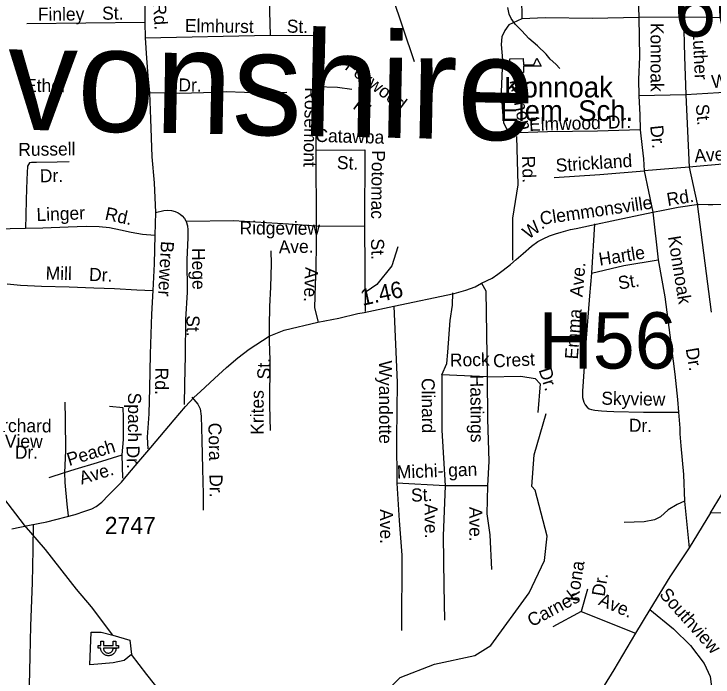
# Model space of a CAD drawing. Extents: x 1553981 to 1780076, y 812965 to 996873.
# Drawn here: x 1632965 to 1633602, y 845527 to 846130 of the extents above; entities that cross this region are included whole.
import ezdxf

# ---------------------------------------------------------------- set-up
doc = ezdxf.new("R2010")
doc.units = 0
for name, color, linetype in [('Exist Aviation Coast Guard Station CELL', 7, 'Continuous'), ('Exist Cultural Educational Facility High Label', 7, 'Continuous'), ('Exist Cultural Historical Site CELL', 7, 'Continuous'), ('Exist Hydrographic Creek Single Shore', 7, 'Continuous'), ('Exist Hydrographic Misc Water Feature', 7, 'Continuous'), ('Exist Road Non-System Type 51 Label', 7, 'Continuous'), ('Exist Road Primary US Structure Non-Sys NCDOT Number Label', 7, 'Continuous'), ('Exist Road Secondary Mileage Hundredths English Label', 7, 'Continuous'), ('Exist Road Secondary Structure Standard Bridge Number Label', 7, 'Continuous'), ('Exist Road Secondary Type 51 Attributed', 7, 'Continuous'), ('Exist Road Secondary Type 51 Number Label', 7, 'Continuous'), ('Exist Utilities Electrical Transmission Line', 7, 'Continuous'), ('Map Preparation Border Antique Large Shape', 7, 'Continuous'), ('Map Preparation Border County Name Lower Right Label', 7, 'Continuous')]:
    doc.layers.add(name, color=color, linetype=linetype)

msp = doc.modelspace()

# ---------------------------------------------------------------- linework, layer by layer
at = {"layer": 'Exist Aviation Coast Guard Station CELL'}
msp.add_lwpolyline([(1633416.81, 846089.49), (1633429.05, 846089.67), (1633429.14, 846083.92), (1633438.52, 846084.06), (1633441.46, 846089.99), (1633445.22, 846082.97), (1633429.15, 846082.72), (1633429.24, 846076.97), (1633417, 846076.78)], close=True, dxfattribs=at)
at = {"layer": 'Exist Cultural Historical Site CELL'}
msp.add_lwpolyline([(1633041.73, 845555.6), (1633044.17, 845555.6), (1633044.17, 845559.63), (1633046.65, 845559.63), (1633046.65, 845555.6), (1633055.5, 845555.6), (1633055.5, 845559.63), (1633057.98, 845559.63), (1633057.98, 845555.6), (1633060.42, 845555.6), (1633060.42, 845553.17), (1633057.98, 845553.17), (1633055.5, 845553.17), (1633046.65, 845553.17), (1633046.73, 845552.4), (1633046.88, 845551.73), (1633047.18, 845551.03), (1633047.65, 845550.36), (1633048.23, 845549.75), (1633048.56, 845549.51), (1633048.94, 845549.3), (1633049.41, 845549.04), (1633049.93, 845548.87), (1633050.53, 845548.75), (1633050.99, 845548.72), (1633051.51, 845548.74), (1633052.1, 845548.83), (1633052.63, 845548.98), (1633053.01, 845549.13), (1633053.42, 845549.35), (1633053.84, 845549.65), (1633054.24, 845550), (1633054.57, 845550.37), (1633054.84, 845550.74), (1633055, 845551.03), (1633055.18, 845551.38), (1633055.35, 845551.82), (1633055.41, 845552.1), (1633055.51, 845552.56), (1633055.54, 845552.92), (1633055.56, 845553.17), (1633058.26, 845553.17), (1633058.22, 845552.74), (1633058.18, 845552.41), (1633058.11, 845552), (1633058.01, 845551.58), (1633057.88, 845551.11), (1633057.75, 845550.72), (1633057.59, 845550.32), (1633057.36, 845549.88), (1633057.07, 845549.43), (1633056.76, 845548.98), (1633056.43, 845548.6), (1633056.1, 845548.26), (1633055.65, 845547.86), (1633055.18, 845547.49), (1633054.65, 845547.18), (1633054.1, 845546.9), (1633053.68, 845546.72), (1633053.29, 845546.59), (1633052.9, 845546.49), (1633052.42, 845546.38), (1633051.96, 845546.33), (1633051.53, 845546.28), (1633050.98, 845546.28), (1633050.6, 845546.3), (1633050.17, 845546.35), (1633049.72, 845546.44), (1633049.12, 845546.58), (1633048.49, 845546.82), (1633047.94, 845547.07), (1633047.49, 845547.33), (1633046.97, 845547.67), (1633046.58, 845548), (1633046.34, 845548.2), (1633046.03, 845548.51), (1633045.79, 845548.79), (1633045.45, 845549.2), (1633045.11, 845549.74), (1633044.87, 845550.2), (1633044.67, 845550.62), (1633044.53, 845551.01), (1633044.33, 845551.66), (1633044.23, 845552.21), (1633044.17, 845552.68), (1633044.13, 845553.17), (1633041.73, 845553.17)], close=True, dxfattribs=at)
at = {"layer": 'Exist Hydrographic Creek Single Shore'}
for points in [[(1633329.83, 846086.82), (1633309.7, 846147.54), (1633282.73, 846197.75)], [(1633273.69, 845479.99), (1633291.58, 845501.65), (1633316.82, 845526.57), (1633348.33, 845538.66), (1633384.82, 845546.53), (1633399.58, 845555.67), (1633434.46, 845603.38), (1633448.33, 845633.05), (1633450.71, 845655.16), (1633439.83, 845696.82), (1633436.7, 845700.17), (1633439.07, 845729.25), (1633449.95, 845766.78)]]:
    msp.add_lwpolyline(points, dxfattribs=at)
at = {"layer": 'Exist Hydrographic Misc Water Feature'}
msp.add_lwpolyline([(1633462.42, 846080.77), (1633458.71, 846084.8), (1633453.49, 846089.33), (1633449.79, 846093.61), (1633441.84, 846101.42), (1633434.15, 846107.97), (1633427.71, 846115.02), (1633421.5, 846121.06), (1633418.04, 846126.09), (1633416.07, 846130.11), (1633414.86, 846136.11)], dxfattribs=at)
at = {"layer": 'Exist Road Secondary Type 51 Attributed'}
msp.add_lwpolyline([(1632963.12, 845661.71), (1632979.22, 845665.01), (1632995.26, 845668.13), (1633020.94, 845674.7), (1633029.82, 845677.7), (1633036.23, 845679.82), (1633040.09, 845682.04), (1633045.1, 845686.14), (1633051.43, 845692.47), (1633063.1, 845704.31), (1633068.81, 845711.18), (1633078.76, 845722.98), (1633089.74, 845735.85), (1633110.97, 845760.98), (1633121.51, 845773.19), (1633129.01, 845781.21), (1633134.94, 845786.77), (1633147.71, 845798.61), (1633158.84, 845808.56), (1633169.01, 845817.31), (1633179.25, 845825.18), (1633197.47, 845836.99), (1633211.17, 845842.53), (1633242, 845849.91), (1633260.97, 845853.6), (1633278.5, 845857.64), (1633284.06, 845858.55), (1633311.25, 845864.47), (1633366.07, 845876.06), (1633376.69, 845879.1), (1633385.3, 845882.07), (1633391.09, 845885.27), (1633400.59, 845890.02), (1633405.86, 845893.5), (1633410.76, 845897.29), (1633417.44, 845902.26), (1633422.56, 845906.79), (1633428.87, 845912.28), (1633436.51, 845918.96), (1633442.37, 845923.27), (1633447.05, 845925.72), (1633452.84, 845928.31), (1633458.41, 845930.24), (1633463.53, 845931.88), (1633472.08, 845934.09), (1633477.18, 845935.14), (1633491.21, 845938.19), (1633513.92, 845942.86), (1633547.03, 845949.91), (1633556.38, 845951.84), (1633570.19, 845954.44), (1633588.84, 845957.1), (1633597.32, 845957.09), (1633601.71, 845957.09), (1633609.34, 845957.39)], dxfattribs=at)
at = {"layer": 'Exist Utilities Electrical Transmission Line'}
for points in [[(1633055.15, 845565.05), (1633035.83, 845590.83), (1633022.08, 845606.79), (1632993.94, 845642.95), (1632974.81, 845665.23), (1632955.95, 845689.75)], [(1633072.35, 845547.29), (1633065.53, 845541.9), (1633055.51, 845539.8), (1633045.24, 845538.96), (1633034.24, 845538.13), (1633035.47, 845567.85), (1633044.7, 845567.71), (1633055.15, 845565.05)], [(1633055.15, 845565.05), (1633070.81, 845560.3), (1633072.35, 845547.29)], [(1633102.52, 845052.3), (1633102.88, 845058.57), (1633107.42, 845124.47), (1633110.13, 845170.89), (1633112.76, 845195.6), (1633114.2, 845223.31), (1633115.03, 845243.53), (1633118.05, 845277.46), (1633121.98, 845335.64), (1633126.04, 845403.79), (1633129.56, 845452.95), (1633129.62, 845473.18), (1633115.46, 845492.41), (1633086.06, 845529.07), (1633072.35, 845547.29)]]:
    msp.add_lwpolyline(points, dxfattribs=at)
at = {"layer": 'Map Preparation Border County Name Lower Right Label'}
for p, q in [((1633426.71, 846173.05), (1633427.7, 846126.04)), ((1633575.03, 846127.38), (1633534.21, 846127.07)), ((1633619.65, 846126.83), (1633575.03, 846127.38)), ((1633622.48, 846059.42), (1633577.09, 846056.8)), ((1633577.09, 846056.8), (1633534.14, 846055.83)), ((1633577.09, 846056.8), (1633580.15, 845991.06)), ((1633284.68, 846006.55), (1633284.33, 845937.57)), ((1633619.6, 845994.64), (1633580.15, 845991.06)), ((1633580.15, 845991.06), (1633539.02, 845987.66)), ((1633580.15, 845991.06), (1633587.34, 845957.42)), ((1633539.02, 845987.66), (1633547.03, 845949.91)), ((1633587.34, 845957.42), (1633600.22, 845859.06)), ((1633547.03, 845949.91), (1633551.98, 845906.73)), ((1633094.19, 845949.77), (1633093.62, 845929.04)), ((1633284.33, 845937.57), (1633284.97, 845859.44)), ((1633494, 845939.29), (1633491.12, 845894.57)), ((1633314.86, 845918.27), (1633309.45, 845901.26)), ((1633309.45, 845901.26), (1633295.54, 845884.24)), ((1633295.54, 845884.24), (1633286.1, 845877.5)), ((1633064.45, 845707.85), (1633063.85, 845729.13)), ((1632997.35, 845708.4), (1633011.17, 845712.92)), ((1633357.88, 845700.95), (1633313.89, 845703.3)), ((1633575.85, 845686.94), (1633580.17, 845644.56)), ((1633599.64, 845676.37), (1633580.17, 845644.56))]:
    msp.add_line(p, q, dxfattribs=at)
for points in [[(1633570.16, 846236.74), (1633573.04, 846170.24), (1633575.03, 846127.38)], [(1633534.1, 846168.98), (1633533.6, 846146), (1633534.21, 846127.07)], [(1633197.29, 846154.82), (1633198.38, 846111.08)], [(1633084.52, 846152.04), (1633084.52, 846122.53)], [(1633084.52, 846122.53), (1632977.01, 846121.49)], [(1633084.52, 846122.53), (1633084.58, 846108.65)], [(1633427.7, 846126.04), (1633415.78, 846120.36), (1633412.28, 846115.42), (1633409.61, 846109.45), (1633408.99, 846102.46), (1633410.23, 846088.47), (1633408.99, 846059.25), (1633410.23, 846041.23), (1633411.06, 846031.56), (1633413.73, 846025.8), (1633416.2, 846021.89)], [(1633534.21, 846127.07), (1633492.15, 846126.25), (1633449.16, 846126.87), (1633427.7, 846126.04)], [(1633534.21, 846127.07), (1633534.96, 846091.22), (1633533.93, 846070.85), (1633534.14, 846055.83)], [(1633575.03, 846127.38), (1633575.85, 846091.58), (1633577.09, 846056.8)], [(1633084.58, 846108.65), (1633198.38, 846111.08)], [(1633198.38, 846111.08), (1633240.54, 846110.8)], [(1633240.54, 846110.8), (1633240.2, 846064.27)], [(1633084.58, 846108.65), (1633085.96, 846090.24), (1633087.01, 846073.92), (1633088.51, 846058.43)], [(1633213.7, 846058.99), (1633196.93, 846058.43), (1633175.14, 846058.99), (1633158.37, 846059.55), (1633137.69, 846058.43), (1633115.9, 846057.87), (1633088.51, 846058.43)], [(1633088.51, 846058.43), (1633089.63, 846034.95), (1633090.19, 846017.61), (1633090.75, 846000.28), (1633092.99, 845976.79), (1633094.19, 845949.77)], [(1633240.2, 846064.27), (1633259.98, 846063.58), (1633272.81, 846061.84)], [(1633240.2, 846064.27), (1633240.21, 846006.42)], [(1633534.14, 846055.83), (1633535.25, 846038.56), (1633535.58, 846024.96)], [(1633535.58, 846024.96), (1633496.59, 846023.54), (1633451.15, 846023.13), (1633416.2, 846021.89)], [(1633535.58, 846024.96), (1633537.17, 846008.86), (1633538.61, 845998.57), (1633539.02, 845987.66)], [(1633422.73, 846018.88), (1633424.09, 845974.88), (1633419.28, 845944.36), (1633419.08, 845906.13)], [(1633240.21, 846006.42), (1633284.68, 846006.55)], [(1633240.21, 846006.42), (1633240.55, 845937.32)], [(1633015.46, 845995.66), (1633004.47, 845995.34), (1632985.73, 845995.12), (1632981.23, 845995.18), (1632979.22, 845994.97), (1632977.43, 845991.73), (1632977.01, 845979.76), (1632976.22, 845961.54), (1632976, 845946.79), (1632975.59, 845935.31)], [(1633457.14, 845981.58), (1633498.64, 845984.24), (1633539.02, 845987.66)], [(1633094.19, 845949.77), (1633101.71, 845951.42), (1633105.31, 845951.69), (1633108.61, 845951.45), (1633111.97, 845950.61), (1633114.65, 845949.45), (1633116.7, 845948.16), (1633118.37, 845946.65), (1633120.35, 845944.26), (1633121.58, 845942.15)], [(1633599.64, 845676.37), (1633646.27, 845752.81), (1633660.34, 845775.98), (1633666.77, 845790.5), (1633670.58, 845802.82), (1633672.92, 845814.84), (1633673.51, 845827.75), (1633673.51, 845865.59), (1633668.81, 845911.16), (1633666.76, 845955.46)], [(1632975.59, 845935.31), (1632991.33, 845935.82), (1633014.56, 845936.72), (1633030.81, 845937.22), (1633042.78, 845936.8), (1633052.27, 845935.91), (1633062.23, 845933.76), (1633071.94, 845931.61), (1633082.14, 845929.98), (1633093.62, 845929.04)], [(1633121.58, 845942.15), (1633122.04, 845941.35), (1633123.16, 845937.52), (1633123.41, 845933.84), (1633123.55, 845926.83), (1633123.2, 845919.86), (1633122.76, 845906.86), (1633123.06, 845877.14), (1633121.34, 845852.29), (1633121.09, 845819.46), (1633120.44, 845793.49), (1633120.3, 845774.85)], [(1633240.55, 845937.32), (1633215.23, 845939.18), (1633165.27, 845941.95), (1633122.24, 845941.61)], [(1633240.55, 845937.32), (1633240.32, 845921.31), (1633239.98, 845898.33), (1633239.39, 845884.18), (1633238.81, 845862.96), (1633242.15, 845849.94)], [(1633240.55, 845937.32), (1633284.33, 845937.57)], [(1632943.6, 845934.29), (1632961.85, 845935.02), (1632975.59, 845935.31)], [(1633093.62, 845929.04), (1633092.97, 845902.82), (1633091.6, 845878.61)], [(1633199.04, 845914.72), (1633199.38, 845902.98), (1633198.8, 845881.73), (1633197.79, 845864.02), (1633197.75, 845846.29), (1633197.54, 845832.31)], [(1633491.12, 845894.57), (1633520.52, 845901.38), (1633551.98, 845906.73)], [(1633551.98, 845906.73), (1633557.94, 845872.98), (1633562.47, 845838.11), (1633567, 845802.51), (1633569.47, 845779.43), (1633570.5, 845767.9)], [(1633491.12, 845894.57), (1633489.42, 845873.84), (1633486.06, 845831.37), (1633482.93, 845787.16), (1633483.11, 845781.15), (1633484.08, 845777.15), (1633485.55, 845774.64), (1633487.28, 845772.38), (1633489.03, 845771.1), (1633491.27, 845770.35), (1633494.11, 845769.62), (1633500.25, 845769.02), (1633504.99, 845768.72), (1633511.49, 845768.41), (1633538.47, 845767.94), (1633570.5, 845767.9)], [(1632959.08, 845884.6), (1632971.06, 845883.4), (1632990.28, 845882.64), (1633015.48, 845882), (1633037.95, 845881.17), (1633056.67, 845880.39), (1633077.13, 845879.32), (1633091.6, 845878.61)], [(1633391.09, 845885.27), (1633394.79, 845878.31), (1633396.25, 845800.25)], [(1633091.6, 845878.61), (1633090.54, 845857.14), (1633089.22, 845820.67), (1633088.5, 845789.72), (1633087.9, 845766.49), (1633086.59, 845745.28), (1633087.09, 845734.67)], [(1633354.94, 845802.04), (1633359.34, 845812.32), (1633360.21, 845822.59), (1633362.56, 845851.35), (1633364.61, 845865.43), (1633364.78, 845876.55)], [(1633311.25, 845864.47), (1633314.18, 845794.91), (1633313.59, 845744.09), (1633313.89, 845703.3)], [(1633197.54, 845832.31), (1633198.16, 845815.63), (1633198.01, 845773.91), (1633198.42, 845751.17)], [(1633354.94, 845802.04), (1633354.94, 845751.43), (1633357.88, 845700.95)], [(1633396.25, 845800.25), (1633354.94, 845802.04)], [(1633396.25, 845800.25), (1633426.75, 845800.83), (1633439.95, 845798.48), (1633444.35, 845793.79), (1633442.29, 845767.67)], [(1633396.25, 845800.25), (1633396.55, 845761.65), (1633397.73, 845723.2), (1633396.55, 845700.9)], [(1633127.1, 845781.56), (1633132.6, 845775.14), (1633134.79, 845770.87), (1633135.68, 845764.35), (1633136.37, 845742.6), (1633136.96, 845716.37), (1633137.37, 845693.37), (1633137.62, 845678.89)], [(1633011.4, 845777.13), (1633011.91, 845761.63), (1633011.98, 845732.89), (1633011.17, 845712.92)], [(1633063.85, 845729.13), (1633064.81, 845743.1), (1633064.87, 845763.33), (1633064.5, 845771.85), (1633052.29, 845773.02)], [(1633570.5, 845767.9), (1633571.75, 845753.3), (1633571.7, 845748.3), (1633572.55, 845737.24), (1633574.81, 845711.11), (1633575.85, 845686.94)], [(1633011.17, 845712.92), (1633020.94, 845716.02), (1633041.28, 845722.21), (1633063.85, 845729.13)], [(1633011.17, 845712.92), (1633011.52, 845703.93), (1633013.47, 845684.16), (1633014.47, 845673.68)], [(1633313.89, 845703.3), (1633316.03, 845669.45), (1633318.31, 845637.71), (1633318.09, 845569.11)], [(1633357.88, 845700.95), (1633356.11, 845655.33), (1633356.7, 845609.84), (1633357.28, 845578.73)], [(1633396.55, 845700.9), (1633357.88, 845700.95)], [(1633396.55, 845700.9), (1633395.96, 845675.48), (1633398.6, 845656.21), (1633400.07, 845624.81)], [(1633575.85, 845686.94), (1633569.06, 845684.06), (1633561.04, 845678.92), (1633554.05, 845672.54), (1633548.5, 845669.86), (1633539.04, 845668.01), (1633520.95, 845667.4)], [(1633687.83, 845675.15), (1633599.64, 845676.37)], [(1632982.66, 845666.1), (1632982.31, 845642.82), (1632981.83, 845612.47), (1632980.14, 845573.5), (1632979.66, 845545.56), (1632978.94, 845519.42), (1632978.22, 845501.12)], [(1633580.17, 845644.56), (1633562.64, 845618.21), (1633544.45, 845588.45)], [(1633487.57, 845606.94), (1633481.8, 845586.43)], [(1633544.45, 845588.45), (1633531.17, 845566.78)], [(1633544.45, 845588.45), (1633565.76, 845570.67), (1633581.35, 845555.65), (1633593.76, 845539.18), (1633599.25, 845527.34), (1633600.98, 845513.47), (1633600.69, 845486.89), (1633600.98, 845449.04)], [(1633481.8, 845586.43), (1633456.1, 845572.56)], [(1633481.8, 845586.43), (1633531.17, 845566.78)], [(1633531.17, 845566.78), (1633511.61, 845533.41), (1633491.4, 845501.05)]]:
    msp.add_lwpolyline(points, dxfattribs=at)

# ---------------------------------------------------------------- texts
at = {"layer": 'Exist Cultural Educational Facility High Label'}
for s, p in [('Konnoak', (1633411.68, 846054.36)), ('Elem. Sch.', (1633407.97, 846033))]:
    msp.add_text(s, height=18.75, dxfattribs=at).set_placement(p)
at = {"layer": 'Exist Road Non-System Type 51 Label'}
for s, height, rotation, p in [('Finley', 11.875, 0.37648, (1632986.94, 846124.14)), ('St.', 11.875, 0.56022, (1633045.52, 846125.06)), ('Rd.', 11.875, 273.85034, (1633091.68, 846140.18)), ('Devonshire', 95, 358.76379, (1632796.19, 846028.75)), ('Elmhurst', 11.875, 359.14646, (1633120.8, 846113.91)), ('St.', 11.875, 358.46822, (1633213.5, 846113.42)), ('Konnoak', 11.875, 270.01923, (1633544.94, 846122.29)), ('Luther', 11.875, 272.64198, (1633583.26, 846115.14)), ('Foxwood', 11.875, 323.10933, (1633265.71, 846080.56)), ('Ethel', 11.875, 359.64336, (1632975.26, 846059.39)), ('Dr.', 11.875, 359.74991, (1633114.94, 846059.82)), ('W.', 11.875, 5.0355, (1633600.92, 846062.78)), ('Renon', 11.875, 281.56932, (1633416.4, 846069.7)), ('Rosemont', 11.875, 268.79123, (1633230.31, 846063.63)), ('Pl.', 11.875, 323.10933, (1633273.03, 846044.84)), ('St.', 11.875, 274.83509, (1633586.13, 846047.88)), ('Elmwood', 11.875, 1.52977, (1633434.44, 846023.89)), ('Dr.', 11.875, 1.45903, (1633506.18, 846025.98)), ('Dr.', 11.875, 275.69149, (1633544.57, 846028.52)), ('Catawba', 11.875, 358.37073, (1633239.62, 846013.98)), ('Russell', 11.875, 0.67331, (1632969.19, 846001.07)), ('Ave.', 11.875, 4.03992, (1633585.23, 845995.31)), ('St.', 11.875, 358.37073, (1633259.17, 845989.24)), ('Potomac', 11.875, 269.26962, (1633291.23, 846006.44)), ('Strickland', 11.875, 3.87231, (1633458.98, 845986.59)), ('Rd.', 11.875, 271.7665, (1633427.77, 846001.09)), ('Dr.', 11.875, 0.67331, (1632988.78, 845977.12)), ('Linger', 11.875, 2.23018, (1632985.94, 845941.77)), ('Rd.', 11.875, 347.80379, (1633047.34, 845943.27)), ('Ridgeview', 11.875, 359.67818, (1633170.62, 845929.76)), ('St.', 11.875, 271.69191, (1633290.25, 845925.83)), ('Konnoak', 11.875, 279.13176, (1633560.68, 845927.52)), ('Brewer', 11.875, 266.90832, (1633099.15, 845923.85)), ('Ave.', 11.875, 1.33528, (1633206.38, 845912.34)), ('Hartle', 11.875, 9.16534, (1633498.72, 845901.13)), ('Hege', 11.875, 270.6467, (1633127.27, 845917.28)), ('Mill', 11.875, 358.55414, (1632993.94, 845888.7)), ('Dr.', 11.875, 357.6139, (1633033.4, 845887.52)), ('Ave.', 11.875, 267.5483, (1633230.46, 845900.11)), ('Ave.', 11.875, 85.32053, (1633483.13, 845872.36)), ('St.', 11.875, 9.16534, (1633516.34, 845879.48)), ('Emma', 11.875, 85.47146, (1633478.65, 845815.74)), ('St.', 11.875, 270.40671, (1633122.32, 845856.12)), ('Rock', 11.875, 1.43564, (1633362.39, 845809.28)), ('Dr.', 11.875, 279.72211, (1633576.88, 845825.63)), ('Crest', 11.875, 2.91473, (1633401.87, 845808.57)), ('St.', 11.875, 89.79893, (1633198.68, 845797.78)), ('Wyandotte', 11.875, 270.23261, (1633297.54, 845814.91)), ('Rd.', 11.875, 269.9633, (1633093.79, 845808.41)), ('Dr.', 11.875, 287.84478, (1633442.89, 845806.41)), ('Clinard', 11.875, 270.47422, (1633336.45, 845799.01)), ('Hastings', 11.875, 270.40528, (1633380.75, 845802.06)), ('Spach', 11.875, 269.82814, (1633069.11, 845785.71)), ('Krites', 11.875, 89.79893, (1633192.5, 845747.38)), ('Skyview', 11.875, 358.99505, (1633500.07, 845774.77)), ('Orchard', 11.875, 359.48731, (1632942.04, 845750.02)), ('Dr.', 11.875, 358.99505, (1633525.1, 845750.15)), ('Cora', 11.875, 271.29617, (1633142.17, 845758.2)), ('View', 11.875, 359.47914, (1632956.85, 845735.73)), ('Peach', 11.875, 16.9328, (1633015.44, 845718.85)), ('Dr.', 11.875, 359.82814, (1632965.96, 845725.56)), ('Dr.', 11.875, 271.60346, (1633067.59, 845737.39)), ('Michi- gan', 11.875, 2.12643, (1633314.12, 845707.48)), ('Ave.', 11.875, 16.9328, (1633026.69, 845701.92)), ('Dr.', 11.875, 271.01863, (1633143.2, 845711.39)), ('St.', 11.875, 2.12643, (1633326.99, 845686.44)), ('Ave.', 11.875, 270.69943, (1633339.08, 845684.73)), ('Ave.', 11.875, 270.45692, (1633298.46, 845679.7)), ('Ave.', 11.875, 270.32584, (1633379.78, 845681.81)), ('Kona', 11.875, 80.84437, (1633478.96, 845595.03)), ('Dr.', 11.875, 80.84437, (1633502.98, 845599.72)), ('Southview', 11.875, 311.91197, (1633552.29, 845601.45)), ('Carnes', 11.875, 28.10463, (1633436.73, 845572.17)), ('Ave.', 11.875, 336.8525, (1633496.66, 845592.88))]:
    msp.add_text(s, height=height, rotation=rotation, dxfattribs=at).set_placement(p)
at = {"layer": 'Exist Road Primary US Structure Non-Sys NCDOT Number Label'}
msp.add_text('H56', height=51.263, dxfattribs=at).set_placement((1633442.87, 845807.61))
at = {"layer": 'Exist Road Secondary Mileage Hundredths English Label'}
msp.add_text('1.46', height=15, rotation=12.34313, dxfattribs=at).set_placement((1633282.54, 845864.7))
at = {"layer": 'Exist Road Secondary Structure Standard Bridge Number Label'}
msp.add_text('60', height=51.263, dxfattribs=at).set_placement((1633566.49, 846109.84))
at = {"layer": 'Exist Road Secondary Type 51 Number Label'}
msp.add_text('2747', height=15.625, dxfattribs=at).set_placement((1633047.91, 845657.03))
at = {"layer": 'Map Preparation Border Antique Large Shape'}
for s, rotation, p in [('Rd.', 9.43983, (1633560.68, 845955.46)), ('Clemmonsville', 8.30676, (1633445.02, 845938.35)), ('W.', 36.88339, (1633433.9, 845924.79))]:
    msp.add_text(s, height=11.875, rotation=rotation, dxfattribs=at).set_placement(p)

doc.saveas('drawing.dxf')
